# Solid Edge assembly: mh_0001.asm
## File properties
Title: magic_hand__study
Author: edge
Template: normal.asm
Last saved by: edge
Revision: 57
Application: Solid Edge
文書内容のタイプ: 1
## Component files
mh_0002.asm
mh_0003.asm
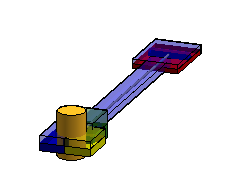
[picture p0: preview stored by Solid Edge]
